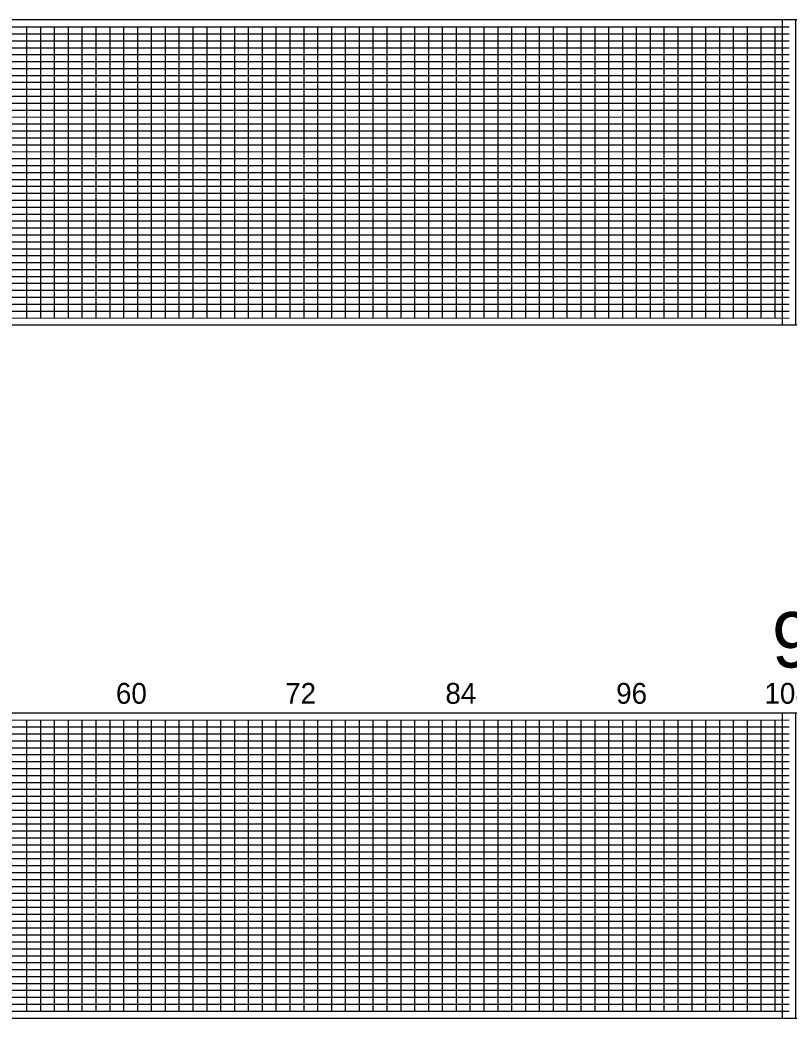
# Model space of a CAD drawing. Extents: x 1870112 to 1888282, y 758439 to 777406.
# Drawn here: x 1880157 to 1882932, y 758439 to 762039 of the extents above; entities that cross this region are included whole.
import ezdxf

# ---------------------------------------------------------------- set-up
doc = ezdxf.new("R2010")
doc.units = 0
for name, color, linetype in [('RD_PD_WallFill', 7, 'Continuous'), ('RD_SHT_IplotShp', 7, 'Continuous'), ('RD_Sketch8', 7, 'Continuous')]:
    doc.layers.add(name, color=color, linetype=linetype)

msp = doc.modelspace()

# ---------------------------------------------------------------- linework, layer by layer
at = {"layer": 'RD_PD_WallFill'}
for p, q in [((1877581.6, 762014.2), (1882931.6, 762014.2)), ((1880181.6, 760964.2), (1880181.6, 762014.2)), ((1880231.6, 760964.2), (1880231.6, 762014.2)), ((1880281.6, 760964.2), (1880281.6, 762014.2)), ((1880331.6, 760964.2), (1880331.6, 762014.2)), ((1880381.6, 760964.2), (1880381.6, 762014.2)), ((1880431.6, 760964.2), (1880431.6, 762014.2)), ((1880481.6, 760964.2), (1880481.6, 762014.2)), ((1880531.6, 760964.2), (1880531.6, 762014.2)), ((1880581.6, 760964.2), (1880581.6, 762014.2)), ((1880631.6, 760964.2), (1880631.6, 762014.2)), ((1880681.6, 760964.2), (1880681.6, 762014.2)), ((1880731.6, 760964.2), (1880731.6, 762014.2)), ((1880781.6, 760964.2), (1880781.6, 762014.2)), ((1880831.6, 760964.2), (1880831.6, 762014.2)), ((1880881.6, 760964.2), (1880881.6, 762014.2)), ((1880931.6, 760964.2), (1880931.6, 762014.2)), ((1880981.6, 760964.2), (1880981.6, 762014.2)), ((1881031.6, 760964.2), (1881031.6, 762014.2)), ((1881081.6, 760964.2), (1881081.6, 762014.2)), ((1881131.6, 760964.2), (1881131.6, 762014.2)), ((1881181.6, 760964.2), (1881181.6, 762014.2)), ((1881231.6, 760964.2), (1881231.6, 762014.2)), ((1881281.6, 760964.2), (1881281.6, 762014.2)), ((1881331.6, 760964.2), (1881331.6, 762014.2)), ((1881381.6, 760964.2), (1881381.6, 762014.2)), ((1881431.6, 760964.2), (1881431.6, 762014.2)), ((1881481.6, 760964.2), (1881481.6, 762014.2)), ((1881531.6, 760964.2), (1881531.6, 762014.2)), ((1881581.6, 760964.2), (1881581.6, 762014.2)), ((1881631.6, 760964.2), (1881631.6, 762014.2)), ((1881681.6, 760964.2), (1881681.6, 762014.2)), ((1881731.6, 760964.2), (1881731.6, 762014.2)), ((1881781.6, 760964.2), (1881781.6, 762014.2)), ((1881831.6, 760964.2), (1881831.6, 762014.2)), ((1881881.6, 760964.2), (1881881.6, 762014.2)), ((1881931.6, 760964.2), (1881931.6, 762014.2)), ((1881981.6, 760964.2), (1881981.6, 762014.2)), ((1882031.6, 760964.2), (1882031.6, 762014.2)), ((1882081.6, 760964.2), (1882081.6, 762014.2)), ((1882131.6, 760964.2), (1882131.6, 762014.2)), ((1882181.6, 760964.2), (1882181.6, 762014.2)), ((1882231.6, 760964.2), (1882231.6, 762014.2)), ((1882281.6, 760964.2), (1882281.6, 762014.2)), ((1882331.6, 760964.2), (1882331.6, 762014.2)), ((1882381.6, 760964.2), (1882381.6, 762014.2)), ((1882431.6, 760964.2), (1882431.6, 762014.2)), ((1882481.6, 760964.2), (1882481.6, 762014.2)), ((1882531.6, 760964.2), (1882531.6, 762014.2)), ((1882581.6, 760964.2), (1882581.6, 762014.2)), ((1882631.6, 760964.2), (1882631.6, 762014.2)), ((1882681.6, 760964.2), (1882681.6, 762014.2)), ((1882731.6, 760964.2), (1882731.6, 762014.2)), ((1882781.6, 760964.2), (1882781.6, 762014.2)), ((1882831.6, 760964.2), (1882831.6, 762014.2)), ((1882881.6, 760964.2), (1882881.6, 762014.2)), ((1878031.6, 761989.2), (1882931.6, 761989.2)), ((1878031.6, 761964.2), (1882931.6, 761964.2)), ((1878031.6, 761939.2), (1882931.6, 761939.2)), ((1878031.6, 761914.2), (1882931.6, 761914.2)), ((1878031.6, 761889.1), (1882931.6, 761889.2)), ((1877581.6, 761864.2), (1882931.6, 761864.2)), ((1877581.6, 761839.2), (1882931.6, 761839.1)), ((1877581.6, 761814.2), (1882931.6, 761814.2)), ((1877581.6, 761789.2), (1882931.6, 761789.1)), ((1877581.6, 761764.2), (1882931.6, 761764.2)), ((1877581.6, 761739.1), (1882931.6, 761739.2)), ((1877581.6, 761714.1), (1882931.6, 761714.2)), ((1877581.6, 761689.2), (1882931.6, 761689.1)), ((1877581.6, 761664.1), (1882931.6, 761664.2)), ((1877581.6, 761639.2), (1882931.6, 761639.2)), ((1877581.6, 761614.2), (1882931.6, 761614.1)), ((1877581.6, 761589.2), (1882931.6, 761589.2)), ((1877581.6, 761564.2), (1882931.6, 761564.1)), ((1877581.6, 761539.2), (1882931.6, 761539.2)), ((1877581.6, 761514.2), (1882931.6, 761514.2)), ((1877581.6, 761489.2), (1882931.6, 761489.1)), ((1877581.6, 761464.2), (1882931.6, 761464.2)), ((1877581.6, 761439.1), (1882931.6, 761439.2)), ((1877581.6, 761414.2), (1882931.6, 761414.2)), ((1877581.6, 761389.2), (1882931.6, 761389.2)), ((1877581.6, 761364.1), (1882931.6, 761364.2)), ((1877581.6, 761339.2), (1882931.6, 761339.1)), ((1877581.6, 761314.2), (1882931.6, 761314.2)), ((1877581.6, 761289.2), (1882931.6, 761289.2)), ((1877581.6, 761264.2), (1882931.6, 761264.1)), ((1877581.6, 761239.2), (1882931.6, 761239.2)), ((1877581.6, 761214.2), (1882931.6, 761214.2)), ((1877581.6, 761189.2), (1882931.6, 761189.2)), ((1877581.6, 761164.2), (1882931.6, 761164.2)), ((1877581.6, 761139.1), (1882931.6, 761139.2)), ((1877581.6, 761114.2), (1882931.6, 761114.1)), ((1877581.6, 761089.2), (1882931.6, 761089.2)), ((1877581.6, 761064.2), (1882931.6, 761064.2)), ((1877581.6, 761039.2), (1882931.6, 761039.2)), ((1877581.6, 761014.2), (1882931.6, 761014.2)), ((1877631.6, 760989.1), (1882931.6, 760989.2)), ((1877581.6, 760964.2), (1882931.6, 760964.1)), ((1877581.6, 759514.1), (1882931.6, 759514.2)), ((1880181.6, 758464.2), (1880181.6, 759514.2)), ((1880231.6, 758464.2), (1880231.6, 759514.2)), ((1880281.6, 758464.2), (1880281.6, 759514.2)), ((1880331.6, 758464.2), (1880331.6, 759514.2)), ((1880381.6, 758464.2), (1880381.6, 759514.2)), ((1880431.6, 758464.2), (1880431.6, 759514.2)), ((1880481.6, 758464.2), (1880481.6, 759514.2)), ((1880531.6, 758464.2), (1880531.6, 759514.2)), ((1880581.6, 758464.2), (1880581.6, 759514.2)), ((1880631.6, 758464.2), (1880631.6, 759514.2)), ((1880681.6, 758464.1), (1880681.6, 759514.2)), ((1880731.6, 758464.2), (1880731.6, 759514.2)), ((1880781.6, 758464.2), (1880781.6, 759514.2)), ((1880831.6, 758464.2), (1880831.6, 759514.2)), ((1880881.6, 758464.2), (1880881.6, 759514.2)), ((1880931.6, 758464.2), (1880931.6, 759514.2)), ((1880981.6, 758464.1), (1880981.6, 759514.2)), ((1881031.6, 758464.1), (1881031.6, 759514.2)), ((1881081.6, 758464.2), (1881081.6, 759514.2)), ((1881131.6, 758464.2), (1881131.6, 759514.2)), ((1881181.6, 758464.2), (1881181.6, 759514.2)), ((1881231.6, 758464.2), (1881231.6, 759514.2)), ((1881281.6, 758464.2), (1881281.6, 759514.2)), ((1881331.6, 758464.2), (1881331.6, 759514.2)), ((1881381.6, 758464.2), (1881381.6, 759514.2)), ((1881431.6, 758464.2), (1881431.6, 759514.2)), ((1881481.6, 758464.2), (1881481.6, 759514.2)), ((1881531.6, 758464.2), (1881531.6, 759514.2)), ((1881581.6, 758464.2), (1881581.6, 759514.2)), ((1881631.6, 758464.2), (1881631.6, 759514.2)), ((1881681.6, 758464.2), (1881681.6, 759514.2)), ((1881731.6, 758464.2), (1881731.6, 759514.2)), ((1881781.6, 758464.2), (1881781.6, 759514.2)), ((1881831.6, 758464.2), (1881831.6, 759514.2)), ((1881881.6, 758464.2), (1881881.6, 759514.2)), ((1881931.6, 758464.2), (1881931.6, 759514.2)), ((1881981.6, 758464.2), (1881981.6, 759514.2)), ((1882031.6, 758464.2), (1882031.6, 759514.2)), ((1882081.6, 758464.2), (1882081.6, 759514.2)), ((1882131.6, 758464.2), (1882131.6, 759514.2)), ((1882181.6, 758464.2), (1882181.6, 759514.2)), ((1882231.6, 758464.2), (1882231.6, 759514.2)), ((1882281.6, 758464.2), (1882281.6, 759514.2)), ((1882331.6, 758464.2), (1882331.6, 759514.2)), ((1882381.6, 758464.2), (1882381.6, 759514.2)), ((1882431.6, 758464.2), (1882431.6, 759514.2)), ((1882481.6, 758464.2), (1882481.6, 759514.2)), ((1882531.6, 758464.2), (1882531.6, 759514.2)), ((1882581.6, 758464.2), (1882581.6, 759514.2)), ((1882631.6, 758464.2), (1882631.6, 759514.2)), ((1882681.6, 758464.2), (1882681.6, 759514.2)), ((1882731.6, 758464.2), (1882731.6, 759514.2)), ((1882781.6, 758464.2), (1882781.6, 759514.2)), ((1882831.6, 758464.2), (1882831.6, 759514.2)), ((1882881.6, 758464.2), (1882881.6, 759514.2)), ((1878031.6, 759489.1), (1882931.6, 759489.1)), ((1878031.6, 759464.1), (1882931.6, 759464.1)), ((1878031.6, 759439.1), (1882931.6, 759439.1)), ((1878031.6, 759414.2), (1882931.6, 759414.1)), ((1878031.6, 759389.1), (1882931.6, 759389.2)), ((1877581.6, 759364.1), (1882931.6, 759364.1)), ((1877581.6, 759339.1), (1882931.6, 759339.1)), ((1877581.6, 759314.1), (1882931.6, 759314.2)), ((1877581.6, 759289.2), (1882931.6, 759289.1)), ((1877581.6, 759264.2), (1882931.6, 759264.2)), ((1877581.6, 759239.1), (1882931.6, 759239.1)), ((1877581.6, 759214.1), (1882931.6, 759214.1)), ((1877581.6, 759189.2), (1882931.6, 759189.1)), ((1877581.6, 759164.1), (1882931.6, 759164.1)), ((1877581.6, 759139.2), (1882931.6, 759139.1)), ((1877581.6, 759114.1), (1882931.6, 759114.1)), ((1877581.6, 759089.1), (1882931.6, 759089.2)), ((1877581.6, 759064.1), (1882931.6, 759064.1)), ((1877581.6, 759039.1), (1882931.6, 759039.2)), ((1877581.6, 759014.1), (1882931.6, 759014.1)), ((1877581.6, 758989.1), (1882931.6, 758989.1)), ((1877581.6, 758964.2), (1882931.6, 758964.1)), ((1877581.6, 758939.1), (1882931.6, 758939.1)), ((1877581.6, 758914.1), (1882931.6, 758914.1)), ((1877581.6, 758889.1), (1882931.6, 758889.1)), ((1877581.6, 758864.1), (1882931.6, 758864.2)), ((1877581.6, 758839.1), (1882931.6, 758839.1)), ((1877581.6, 758814.1), (1882931.6, 758814.1)), ((1877581.6, 758789.1), (1882931.6, 758789.1)), ((1877581.6, 758764.1), (1882931.6, 758764.1)), ((1877581.6, 758739.1), (1882931.6, 758739.1)), ((1877581.6, 758714.1), (1882931.6, 758714.1)), ((1877581.6, 758689.1), (1882931.6, 758689.1)), ((1877581.6, 758664.1), (1882931.6, 758664.1)), ((1877581.6, 758639.1), (1882931.6, 758639.1)), ((1877581.6, 758614.1), (1882931.6, 758614.1)), ((1877581.6, 758589.1), (1882931.6, 758589.1)), ((1877581.6, 758564.1), (1882931.6, 758564.1)), ((1877581.6, 758539.1), (1882931.6, 758539.1)), ((1877581.6, 758514.1), (1882931.6, 758514.1)), ((1877631.6, 758489.1), (1882931.6, 758489.1)), ((1877581.6, 758464.1), (1882931.6, 758464.1))]:
    msp.add_line(p, q, dxfattribs=at)
at = {"layer": 'RD_SHT_IplotShp'}
for points in [[(1877556.6, 760939.2), (1882956.6, 760939.2), (1882956.6, 762039.2), (1877556.6, 762039.2)], [(1882906.6, 760939.2), (1884656.6, 760939.2), (1884656.6, 762039.2), (1882906.6, 762039.2)], [(1877556.6, 758439.1), (1882956.6, 758439.1), (1882956.6, 759539.1), (1877556.6, 759539.1)], [(1882906.6, 758439.2), (1884656.6, 758439.2), (1884656.6, 759539.2), (1882906.6, 759539.2)]]:
    msp.add_lwpolyline(points, close=True, dxfattribs=at)

# ---------------------------------------------------------------- texts
at = {"layer": 'RD_PD_WallFill'}
for s, p in [('60', (1880502.8, 759572.8)), ('72', (1881113.4, 759572.8)), ('84', (1881691.7, 759572.8)), ('96', (1882307.8, 759572.8)), ('108', (1882842.8, 759572.8))]:
    msp.add_text(s, height=75, dxfattribs=at).set_placement(p)
at = {"layer": 'RD_Sketch8'}
msp.add_text('9', height=200, dxfattribs=at).set_placement((1882869.8, 759703.5))

doc.saveas('drawing.dxf')
